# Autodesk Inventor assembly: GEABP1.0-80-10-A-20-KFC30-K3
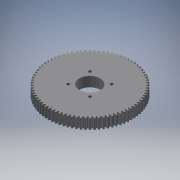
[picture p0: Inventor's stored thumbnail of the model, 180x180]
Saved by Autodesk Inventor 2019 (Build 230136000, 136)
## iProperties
Category: PARTsolutions
Company: MISUMI
Created: 2022-11
Part Number: GEABP1.0-80-10-A-20-KFC30-K3
Catalog Web Link: www.cadenas.de
Description: GEABM, GEABMS, GEABMT, GEABP, GEABPS, GEABPT, GEABA, GEABAS, GEABAT-Plastic Spur Gears - Pressure Angle 20 Degrees, Module 0.5/0.8/1.0/1.5/2.0/2.5/3.0
Vendor: MISUMI
Document SubType Name: Assembly
Designer: psAdmin
Manufacturer: MISUMI
Mass: 46.6006 g
Surface Area: 152.098 cm^2
Volume: 46.6006 cm^3
Density: 1 g/cm^3
Title: GEABP1.0-80-10-A-20-KFC30-K3
Author: Cadenas PARTsolutions
Comments: Plastic Spur Gears - Pressure Angle 20 Degrees, Module 0.5/0.8/1.0/1.5/2.0/2.5/3.0
PSOL_IDENT_0: {$CADENAS_DATA/23d-libs/misumi/metric/54_spur_gears/geabms20_asmtab.prj},415 {VTYP=3D},{STYP=ASSTAB}
PSOL_IDENT_1: ,{NB=GEABP1.0-80-10-A-20-KFC30-K3},{LINA=GEABP1.0-80-10-A-20-KFC30-K3},{NN=GEABM, GEABMS, GEABMT, GE
PSOL_IDENT_2: ABP, GEABPS, GEABPT, GEABA, GEABAS, GEABAT},{DATE=16.08.2021 10:08:31},{GEOMDATE=16.08.2021 10:08:28
PSOL_IDENT_3: },{VERSION=},{LINEID=30},{WBVAR=MATSG,MATCR,NT,B,TS,PS,ALT1,ALT2,TPC,ALT11,ALT10,BS,ALT3,Z,J,ALT4,Q,
PSOL_IDENT_4: R,S,T,ALT5,LFC,LTC,MALT5,ALT6,KFC,KTC,K},{WBNUMERIC=NT,B,BS,Z,J,Q,R,S,T,LFC,LTC,KFC,KTC,K}  {NB=GEAB
PSOL_IDENT_5: P1.0-80-10-A-20-KFC30-K3},{LINA=GEABP1.0-80-10-A-20-KFC30-K3},{KT=DUMMY},{PN=GEABP1.0-80-10-A-20-KFC
PSOL_IDENT_6: 30-K3},{TYPE=GEABP},{MATSG=PW},{MATSGALG='MCN','MC Nylon','PW','Polyacetal White','PB','Polyacetal B
PSOL_IDENT_7: lue'},{MATCR=},{MATCRALG='','-','S45C','1045 Carbon Steel','SUS304','304 Stainless Steel'},{MOD=1.0}
PSOL_IDENT_8: ,{MOD1=1.0},{NT=80},{NTALG=15,16,18,20,22,24,25,26,28,30,32,35,36,40,45,48,50,55,60,70,75,80,90,100,
PSOL_IDENT_9: 120},{B=10},{BALG=10,15},{TS=A},{TSALG='A','A','B','B'},{TSPN=-A},{PS=20},{PSALG='10','10','11','11'
PSOL_IDENT_10: ,'12','12','13','13','14','14','15','15','16','16','17','17','18','18','19','19','20','20','21','21'
PSOL_IDENT_11: ,'22','22','23','23','24','24','25','25','26','26','27','27','28','28'},{PSCRL='10','10','11','11','
PSOL_IDENT_12: 12','12','13','13','14','14','15','15','16','16','17','17','18','18','19','19','20','20','21','21','
PSOL_IDENT_13: 22','22','23','23','24','24','25','25','26','26','27','27','28','28'},{PSCRW='10','10','12','12','15'
PSOL_IDENT_14: ,'15','20','20'},{DD=80.0},{DD05=40},{DD08=64},{DD10=80},{DD15=120},{DD20=0},{DD25=0},{DD30=0},{D=82
PSOL_IDENT_15: .0},{D05=41},{D08=65.6},{D10=82},{D15=123},{D20=0},{D25=0},{D30=0},{G=77.50},{G05=38.75},{G08=62},{G
PSOL_IDENT_16: 10=77.5},{G15=116.25},{G20=0},{G25=0},{G30=0},{H=0.0},{L=0},{LL1=0},{LL2=0.0},{M=-},{M3D=0},{P=20.00
PSOL_IDENT_17: },{DD1=0},{CIFR=15},{CIFM=0},{CIFK=0},{CIFTAP=0},{SCREW=0.000},{SCREWL=0.000},{ALT1=},{ALT1ALG='','N
PSOL_IDENT_18: ot applicable'},{ALT1PN=},{ALT2=},{ALT2ALG='','Not applicable'},{TPC=N/A},{TPCALG='N/A'},{ALT2PN=},{
PSOL_IDENT_19: KC=0},{ALT11=},{ALT11ALG='','Not applicable'},{ALT11PN=},{DEG=0},{ALT10=},{ALT10ALG= '','Not applica
PSOL_IDENT_20: ble' },{ALT10PN=},{BS=0.0},{BSALG=0},{BSMIN=3.000},{BSMINALG=3},{BSMAX=0},{LL13D=0},{LL23D=0},{ALT3=
PSOL_IDENT_21: },{ALT3ALG= '','w/o Stepped Hole','DHL','with DHL (Stepped Hole)','DHR','with DHR (Stepped Hole)' },
PSOL_IDENT_22: {ALT3PN=},{ZJPN=},{ALT31=1},{ALT32=1},{Z=0},{ZALG=0},{ZMINL=22},{ZMAXL=73},{ZMINR=22},{ZMAXR=73},{ZP
PSOL_IDENT_23: N=},{J=0.0},{JALG=0},{JMIN=2},{JMAX=0},{JPN=},{ALT4=},{ALT4ALG= '','w/o WDH (Both Ends Stepped Hole)'
PSOL_IDENT_24: ,'WDH','with WDH (Both Ends Stepped Hole)' },{ALT4PN=},{QRSTPN=},{LB=10.000},{Q=0},{QALG=0},{QMIN=22
PSOL_IDENT_25: },{QMAX=73},{QPN=},{R=0},{RALG=0},{RMIN=22},{RMAX=73},{RPN=},{S=0},{SALG=0},{SMIN=3},{SMAX=4},{SPN=}
PSOL_IDENT_26: ,{T=0},{TALG=0},{TMIN=3},{TMAX=0},{TPN=},{ALT5=},{ALT5ALG= '','w/o Side Slotted Hole','LFC','with LF
PSOL_IDENT_27: C (Side Slotted Hole)','LTC','with LTC (Side Slotted Hole)' },{LFC=0},{LFCALG=0},{LTC=0},{LTCALG=0},
PSOL_IDENT_28: {LPCDMIN=28},{LPCDMAX=70},{LCMAX=73},{MALT5=N/A},{MALT5ALG= 'N/A' },{LCMAX2=70},{C=0.0},{ALT5PN=},{A
PSOL_IDENT_29: LT6=KFC},{ALT6ALG= '','w/o Side Through Hole','KFC','with KFC (Side Through Hole)','KTC','with KTC (
PSOL_IDENT_30: Side Through Hole)' },{ALT6PN=-KFC},{KFTCPN=30-K3},{KFC=30},{KFCALG=[27:70/1]},{KFCPN=30},{KTC=0},{K
PSOL_IDENT_31: TCALG=[0]},{KTCPN=},{KPCDMIN1=27},{KPCDMAX1=-7},{KPCDMIN2=7},{KPCDMAX2=70},{K=3.0},{KALG=[3:6/0.5]},
PSOL_IDENT_32: {KPCD=30},{KPN=-K3},{AG=0},{LBS=10},{PCD=30},{SHN=4},{SHDEG1=45},{SHDEG2=90},{PZQRDD2=20},{PPATH=gea
PSOL_IDENT_33: bms20/geabms20_asmtpl.prj}
NB: GEABP1.0-80-10-A-20-KFC30-K3
NN: GEABM, GEABMS, GEABMT, GEABP, GEABPS, GEABPT, GEABA, GEABAS, GEABAT
NT: 80
NBSYN: $PN.
LINA: GEABP1.0-80-10-A-20-KFC30-K3
CATALOG: Misumi
PN: GEABP1.0-80-10-A-20-KFC30-K3
MATSG: Polyacetal White
MATCR: -
MOD: 1.0
B: 10
TS: A
PS: 20
DD: 80
D: 82
G: 77.5
H: 0
L: 0
LL1: 0
LL2: 0
M: -
DD1: 0
ALT1: Not applicable
ALT2: Not applicable
TPC: N/A
ALT11: Not applicable
ALT10: Not applicable
BS: 0
ALT3: w/o Stepped Hole
Z: 0
J: 0
ALT4: w/o WDH (Both Ends Stepped Hole)
Q: 0
R: 0
S: 0
T: 0
ALT5: w/o Side Slotted Hole
LFC: 0
LTC: 0
MALT5: N/A
C: 0
ALT6: with KFC (Side Through Hole)
KFC: 30
KTC: 0
K: 3
SUPPLIER: MISUMI
ARTICLENO: GEABP1.0-80-10-A-20-KFC30-K3
BOMINFO: GEABP1.0-80-10-A-20-KFC30-K3
CREATOR: CADENAS GmbH
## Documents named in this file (2)
- e:\temp\worker_COMMON_10\temp\tmp_1500_54_Umf9k\format_0\GEABP1_0-80-10-A-20-KFC30-K3.iam
- e:\temp\worker_COMMON_10\temp\tmp_1500_54_Umf9k\format_0\GEABP1_0-80-10-A-20-KFC30-K3_b.ipt
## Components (1 placed, 1 different names)
1. GEABP1_0-80-10-A-20-KFC30-K3_b:1
